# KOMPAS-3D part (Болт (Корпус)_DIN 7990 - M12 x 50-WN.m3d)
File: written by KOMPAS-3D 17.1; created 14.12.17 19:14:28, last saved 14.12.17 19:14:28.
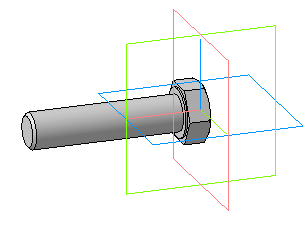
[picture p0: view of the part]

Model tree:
1. Операция без истории:1  (labels: Болт (Корпус)_DIN 7990 - M12 x 50-WN)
